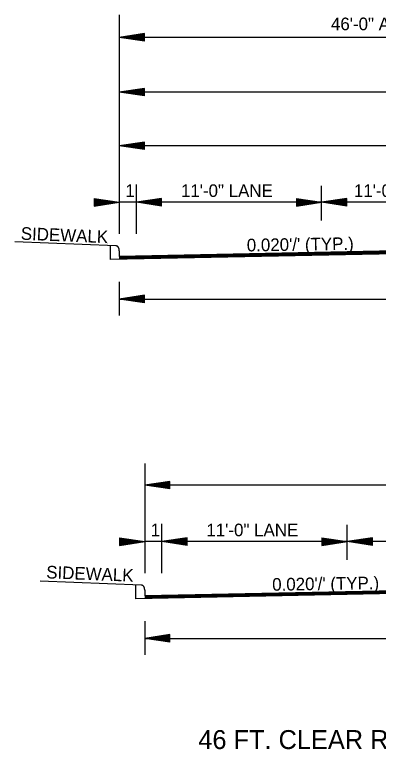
# Model space of a CAD drawing. Extents: x 544199 to 1930787, y -1968972 to 596640.
# Drawn here: x 546456.3 to 546672.1, y -1952177.2 to -1951740.7 of the extents above; entities that cross this region are included whole.
import ezdxf

# ---------------------------------------------------------------- set-up
doc = ezdxf.new("R2010")
doc.units = 0
doc.layers.add('R_Border', color=7, linetype='Continuous')
doc.layers.add('R_Draft', color=7, linetype='Continuous')

msp = doc.modelspace()

# ---------------------------------------------------------------- linework, layer by layer
at = {"layer": 'R_Border'}
for p, q in [((546508.47, -1951852.18), (546508.35, -1951852.18)), ((546516.2, -1951878.06), (546456.25, -1951875.75)), ((546513.19, -1951886.16), (546513.19, -1951877.97)), ((546523.56, -1952053.77), (546523.43, -1952053.77)), ((546531.28, -1952079.65), (546471.34, -1952077.34)), ((546528.15, -1952087.76), (546528.15, -1952079.88))]:
    msp.add_line(p, q, dxfattribs=at)
for points in [[(546518.35, -1951881.04), (546518.27, -1951878.1), (546516.2, -1951878.06)], [(546533.43, -1952082.64), (546533.35, -1952079.69), (546531.28, -1952079.65)]]:
    msp.add_open_spline(points, degree=2, dxfattribs=at)
at = {"layer": 'R_Draft'}
for p, q in [((546518.35, -1951740.71), (546518.35, -1951870.84)), ((546533.35, -1951751.92), (546518.35, -1951754.17)), ((546533.35, -1951752.3), (546520.85, -1951754.17)), ((546533.35, -1951752.68), (546523.43, -1951754.17)), ((546533.35, -1951753.05), (546525.93, -1951754.17)), ((546533.35, -1951756.42), (546533.35, -1951751.92)), ((546978.6, -1951754.17), (546518.35, -1951754.17)), ((546533.35, -1951756.42), (546518.35, -1951754.17)), ((546533.35, -1951756.05), (546520.85, -1951754.17)), ((546533.35, -1951755.66), (546523.43, -1951754.17)), ((546533.35, -1951755.29), (546525.93, -1951754.17)), ((546533.35, -1951753.44), (546528.47, -1951754.17)), ((546533.35, -1951754.9), (546528.47, -1951754.17)), ((546533.35, -1951753.82), (546530.98, -1951754.17)), ((546533.35, -1951754.52), (546530.98, -1951754.17)), ((546533.35, -1951784.51), (546518.35, -1951786.76)), ((546978.6, -1951786.76), (546518.35, -1951786.76)), ((546533.35, -1951789.01), (546518.35, -1951786.76)), ((546533.35, -1951784.88), (546520.85, -1951786.76)), ((546533.35, -1951788.63), (546520.85, -1951786.76)), ((546533.35, -1951785.27), (546523.43, -1951786.76)), ((546533.35, -1951788.25), (546523.43, -1951786.76)), ((546533.35, -1951785.64), (546525.93, -1951786.76)), ((546533.35, -1951787.88), (546525.93, -1951786.76)), ((546533.35, -1951786.02), (546528.47, -1951786.76)), ((546533.35, -1951787.49), (546528.47, -1951786.76)), ((546533.35, -1951786.41), (546530.98, -1951786.76)), ((546533.35, -1951787.11), (546530.98, -1951786.76)), ((546533.35, -1951789.01), (546533.35, -1951784.51)), ((546533.35, -1951816.39), (546518.35, -1951818.64)), ((546533.35, -1951820.89), (546518.35, -1951818.64)), ((546978.6, -1951818.64), (546518.35, -1951818.64)), ((546533.35, -1951816.77), (546520.85, -1951818.64)), ((546533.35, -1951820.52), (546520.85, -1951818.64)), ((546533.35, -1951817.15), (546523.43, -1951818.64)), ((546533.35, -1951820.13), (546523.43, -1951818.64)), ((546533.35, -1951817.52), (546525.93, -1951818.64)), ((546533.35, -1951819.76), (546525.93, -1951818.64)), ((546533.35, -1951817.91), (546528.47, -1951818.64)), ((546533.35, -1951819.37), (546528.47, -1951818.64)), ((546533.35, -1951818.29), (546530.98, -1951818.64)), ((546533.35, -1951818.99), (546530.98, -1951818.64)), ((546533.35, -1951820.89), (546533.35, -1951816.39)), ((546528.47, -1951870.84), (546528.47, -1951842.29)), ((546638.47, -1951863.05), (546638.47, -1951842.29)), ((546503.35, -1951849.93), (546518.35, -1951852.18)), ((546503.35, -1951849.93), (546503.35, -1951854.43)), ((546503.35, -1951850.3), (546515.84, -1951852.18)), ((546503.35, -1951850.69), (546513.26, -1951852.18)), ((546503.35, -1951851.06), (546510.76, -1951852.18)), ((546503.35, -1951851.45), (546508.22, -1951852.18)), ((546503.35, -1951851.83), (546505.72, -1951852.18)), ((546503.35, -1951854.43), (546518.35, -1951852.18)), ((546503.35, -1951852.91), (546508.22, -1951852.18)), ((546503.35, -1951853.67), (546513.26, -1951852.18)), ((546503.35, -1951854.05), (546515.84, -1951852.18)), ((546503.35, -1951853.3), (546510.76, -1951852.18)), ((546503.35, -1951852.53), (546505.72, -1951852.18)), ((546628.47, -1951852.18), (546518.35, -1951852.18)), ((546543.47, -1951849.93), (546528.47, -1951852.18)), ((546543.47, -1951854.43), (546528.47, -1951852.18)), ((546543.47, -1951850.3), (546530.98, -1951852.18)), ((546543.47, -1951854.05), (546530.98, -1951852.18)), ((546543.47, -1951850.69), (546533.56, -1951852.18)), ((546543.47, -1951853.67), (546533.56, -1951852.18)), ((546543.47, -1951851.06), (546536.05, -1951852.18)), ((546543.47, -1951853.3), (546536.05, -1951852.18)), ((546543.47, -1951851.44), (546538.6, -1951852.18)), ((546543.47, -1951852.91), (546538.6, -1951852.18)), ((546543.47, -1951851.83), (546541.1, -1951852.18)), ((546543.47, -1951852.53), (546541.1, -1951852.18)), ((546543.47, -1951854.43), (546543.47, -1951849.93)), ((546623.47, -1951849.93), (546638.47, -1951852.18)), ((546623.47, -1951849.93), (546623.47, -1951854.43)), ((546623.47, -1951850.3), (546635.97, -1951852.18)), ((546623.47, -1951850.69), (546633.39, -1951852.18)), ((546623.47, -1951851.06), (546630.89, -1951852.18)), ((546623.47, -1951851.45), (546628.35, -1951852.18)), ((546623.47, -1951851.83), (546625.84, -1951852.18)), ((546623.47, -1951854.43), (546638.47, -1951852.18)), ((546623.47, -1951852.91), (546628.35, -1951852.18)), ((546623.47, -1951853.67), (546633.39, -1951852.18)), ((546623.47, -1951854.05), (546635.97, -1951852.18)), ((546623.47, -1951853.3), (546630.89, -1951852.18)), ((546623.47, -1951852.53), (546625.84, -1951852.18)), ((546748.47, -1951852.18), (546628.47, -1951852.18)), ((546653.47, -1951849.93), (546638.47, -1951852.18)), ((546653.47, -1951854.43), (546638.47, -1951852.18)), ((546653.47, -1951850.3), (546640.98, -1951852.18)), ((546653.47, -1951854.05), (546640.98, -1951852.18)), ((546653.47, -1951850.69), (546643.56, -1951852.18)), ((546653.47, -1951853.67), (546643.56, -1951852.18)), ((546653.47, -1951851.06), (546646.05, -1951852.18)), ((546653.47, -1951853.3), (546646.05, -1951852.18)), ((546653.47, -1951851.44), (546648.6, -1951852.18)), ((546653.47, -1951852.91), (546648.6, -1951852.18)), ((546653.47, -1951851.83), (546651.1, -1951852.18)), ((546653.47, -1951852.53), (546651.1, -1951852.18)), ((546653.47, -1951854.43), (546653.47, -1951849.93)), ((546748.47, -1951879.78), (546518.35, -1951884.39)), ((546748.5, -1951881.45), (546513.19, -1951886.16)), ((546748.48, -1951880.08), (546518.35, -1951884.69)), ((546748.48, -1951880.38), (546518.35, -1951884.99)), ((546748.49, -1951880.68), (546518.35, -1951885.29)), ((546748.49, -1951880.98), (546518.35, -1951885.59)), ((546518.35, -1951881.04), (546518.35, -1951882.72)), ((546748.5, -1951881.28), (546518.35, -1951885.89)), ((546518.35, -1951882.72), (546518.35, -1951884.39)), ((546518.35, -1951899.39), (546518.35, -1951919.39)), ((546533.35, -1951907.39), (546518.35, -1951909.64)), ((546518.35, -1951909.64), (546978.6, -1951909.64)), ((546533.35, -1951911.89), (546518.35, -1951909.64)), ((546533.35, -1951907.77), (546520.85, -1951909.64)), ((546533.35, -1951911.52), (546520.85, -1951909.64)), ((546533.35, -1951908.15), (546523.43, -1951909.64)), ((546533.35, -1951911.14), (546523.43, -1951909.64)), ((546533.35, -1951908.53), (546525.93, -1951909.64)), ((546533.35, -1951910.76), (546525.93, -1951909.64)), ((546533.35, -1951908.91), (546528.47, -1951909.64)), ((546533.35, -1951910.37), (546528.47, -1951909.64)), ((546533.35, -1951909.29), (546530.98, -1951909.64)), ((546533.35, -1951910), (546530.98, -1951909.64)), ((546533.35, -1951911.89), (546533.35, -1951907.39)), ((546533.43, -1952007.37), (546533.43, -1952072.43)), ((546548.43, -1952017.98), (546533.43, -1952020.23)), ((546548.43, -1952018.36), (546535.94, -1952020.23)), ((546548.43, -1952018.74), (546538.52, -1952020.23)), ((546548.43, -1952019.12), (546541.01, -1952020.23)), ((546548.43, -1952019.5), (546543.56, -1952020.23)), ((546548.43, -1952022.48), (546548.43, -1952017.98)), ((546548.43, -1952022.48), (546533.43, -1952020.23)), ((546993.68, -1952020.23), (546533.43, -1952020.23)), ((546548.43, -1952022.11), (546535.94, -1952020.23)), ((546548.43, -1952021.73), (546538.52, -1952020.23)), ((546548.43, -1952021.35), (546541.01, -1952020.23)), ((546548.43, -1952020.96), (546543.56, -1952020.23)), ((546548.43, -1952019.88), (546546.06, -1952020.23)), ((546548.43, -1952020.59), (546546.06, -1952020.23)), ((546543.56, -1952072.43), (546543.56, -1952043.88)), ((546653.56, -1952064.65), (546653.56, -1952043.88)), ((546518.43, -1952051.52), (546533.43, -1952053.77)), ((546518.43, -1952051.52), (546518.43, -1952056.02)), ((546518.43, -1952051.9), (546530.93, -1952053.77)), ((546518.43, -1952052.28), (546528.35, -1952053.77)), ((546518.43, -1952052.65), (546525.85, -1952053.77)), ((546518.43, -1952053.04), (546523.31, -1952053.77)), ((546518.43, -1952053.42), (546520.8, -1952053.77)), ((546518.43, -1952056.02), (546533.43, -1952053.77)), ((546518.43, -1952054.51), (546523.31, -1952053.77)), ((546518.43, -1952055.26), (546528.35, -1952053.77)), ((546518.43, -1952055.65), (546530.93, -1952053.77)), ((546518.43, -1952054.89), (546525.85, -1952053.77)), ((546518.43, -1952054.12), (546520.8, -1952053.77)), ((546643.56, -1952053.77), (546533.43, -1952053.77)), ((546558.56, -1952051.52), (546543.56, -1952053.77)), ((546558.56, -1952056.02), (546543.56, -1952053.77)), ((546558.56, -1952051.9), (546546.06, -1952053.77)), ((546558.56, -1952055.65), (546546.06, -1952053.77)), ((546558.56, -1952052.28), (546548.64, -1952053.77)), ((546558.56, -1952055.26), (546548.64, -1952053.77)), ((546558.56, -1952052.65), (546551.14, -1952053.77)), ((546558.56, -1952054.89), (546551.14, -1952053.77)), ((546558.56, -1952053.04), (546553.68, -1952053.77)), ((546558.56, -1952054.5), (546553.68, -1952053.77)), ((546558.56, -1952053.42), (546556.19, -1952053.77)), ((546558.56, -1952054.12), (546556.19, -1952053.77)), ((546558.56, -1952056.02), (546558.56, -1952051.52)), ((546638.56, -1952051.52), (546653.56, -1952053.77)), ((546638.56, -1952051.52), (546638.56, -1952056.02)), ((546638.56, -1952051.9), (546651.05, -1952053.77)), ((546638.56, -1952052.28), (546648.47, -1952053.77)), ((546638.56, -1952052.65), (546645.97, -1952053.77)), ((546638.56, -1952053.04), (546643.43, -1952053.77)), ((546638.56, -1952053.42), (546640.93, -1952053.77)), ((546638.56, -1952056.02), (546653.56, -1952053.77)), ((546638.56, -1952054.51), (546643.43, -1952053.77)), ((546638.56, -1952055.26), (546648.47, -1952053.77)), ((546638.56, -1952055.65), (546651.05, -1952053.77)), ((546638.56, -1952054.89), (546645.97, -1952053.77)), ((546638.56, -1952054.12), (546640.93, -1952053.77)), ((546763.56, -1952053.77), (546643.56, -1952053.77)), ((546668.56, -1952051.52), (546653.56, -1952053.77)), ((546668.56, -1952056.02), (546653.56, -1952053.77)), ((546668.56, -1952051.9), (546656.06, -1952053.77)), ((546668.56, -1952055.65), (546656.06, -1952053.77)), ((546668.56, -1952052.28), (546658.64, -1952053.77)), ((546668.56, -1952055.26), (546658.64, -1952053.77)), ((546668.56, -1952052.65), (546661.14, -1952053.77)), ((546668.56, -1952054.89), (546661.14, -1952053.77)), ((546668.56, -1952053.04), (546663.68, -1952053.77)), ((546668.56, -1952054.5), (546663.68, -1952053.77)), ((546668.56, -1952053.42), (546666.19, -1952053.77)), ((546668.56, -1952054.12), (546666.19, -1952053.77)), ((546668.56, -1952056.02), (546668.56, -1952051.52)), ((546763.59, -1952083.05), (546528.15, -1952087.76)), ((546763.56, -1952081.38), (546533.43, -1952085.98)), ((546763.56, -1952081.68), (546533.43, -1952086.28)), ((546763.57, -1952081.98), (546533.43, -1952086.58)), ((546763.57, -1952082.28), (546533.43, -1952086.88)), ((546763.58, -1952082.58), (546533.43, -1952087.18)), ((546533.43, -1952082.64), (546533.43, -1952084.31)), ((546763.59, -1952082.88), (546533.43, -1952087.48)), ((546533.43, -1952084.31), (546533.43, -1952085.98)), ((546533.43, -1952100.99), (546533.43, -1952120.99)), ((546548.43, -1952108.99), (546533.43, -1952111.24)), ((546533.43, -1952111.24), (546993.68, -1952111.24)), ((546548.43, -1952113.49), (546533.43, -1952111.24)), ((546548.43, -1952109.36), (546535.94, -1952111.24)), ((546548.43, -1952113.11), (546535.94, -1952111.24)), ((546548.43, -1952109.74), (546538.52, -1952111.24)), ((546548.43, -1952112.73), (546538.52, -1952111.24)), ((546548.43, -1952110.12), (546541.01, -1952111.24)), ((546548.43, -1952112.35), (546541.01, -1952111.24)), ((546548.43, -1952110.5), (546543.56, -1952111.24)), ((546548.43, -1952111.96), (546543.56, -1952111.24)), ((546548.43, -1952110.88), (546546.06, -1952111.24)), ((546548.43, -1952111.59), (546546.06, -1952111.24)), ((546548.43, -1952113.49), (546548.43, -1952108.99))]:
    msp.add_line(p, q, dxfattribs=at)

# ---------------------------------------------------------------- texts
for s, height, p in [('46\'-0" ACHM SURFACE COURSE (1/2")', 7.5, (546644, -1951749.93)), ("1'", 7.5, (546521.89, -1951849.01)), ('11\'-0" LANE', 7.5, (546554.95, -1951849.01)), ('11\'-0" LANE', 7.5, (546657.61, -1951849.01)), ("1'", 7.5, (546536.98, -1952050.6)), ('11\'-0" LANE', 7.5, (546570.04, -1952050.6)), ('46 FT. CLEAR ROADWAY BRIDGE - POLYMER OVERLAY', 11.25, (546565.26, -1952177.01))]:
    msp.add_text(s, height=height, dxfattribs=at).set_placement(p)
for s, rotation, p in [('SIDEWALK', 357.6795, (546459.75, -1951874.37)), ("0.020'/' (TYP.)", 0.8719, (546594.09, -1951881.38)), ('SIDEWALK', 357.7153, (546474.86, -1952075.56)), ("0.020'/' (TYP.)", 0.8719, (546609.17, -1952082.97))]:
    msp.add_text(s, height=7.5, rotation=rotation, dxfattribs=at).set_placement(p)

doc.saveas('drawing.dxf')
